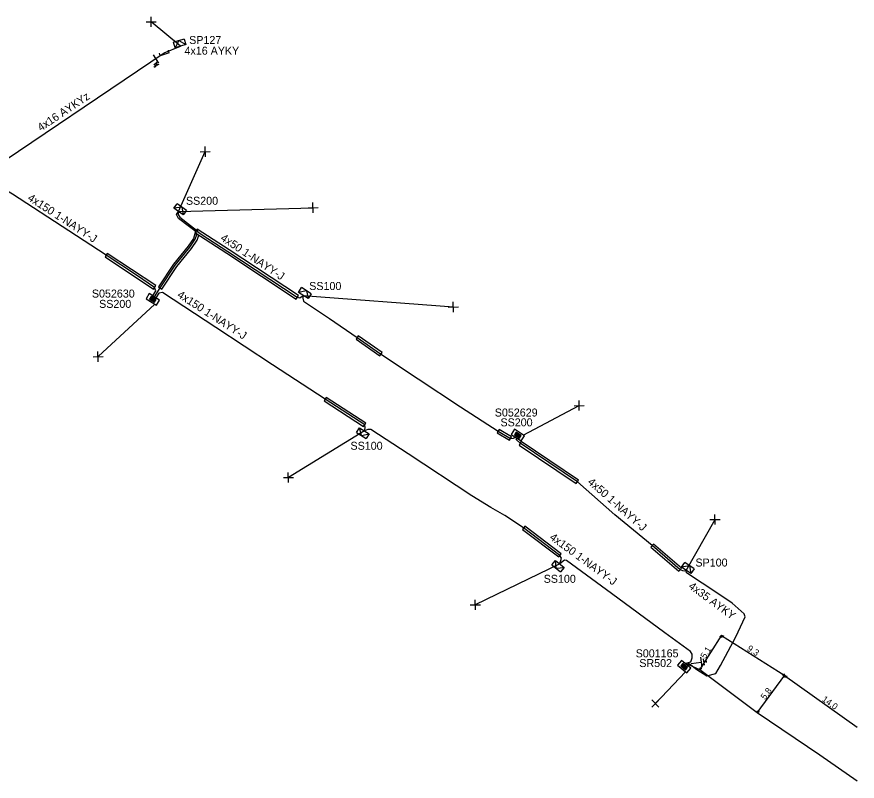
# Model space of a CAD drawing. Extents: x -762504 to -761250, y -1152974 to -1152253.
# Drawn here: x -761354.4 to -761250, y -1152626.9 to -1152531.9 of the extents above; entities that cross this region are included whole.
import ezdxf

# ---------------------------------------------------------------- set-up
doc = ezdxf.new("R2010")
doc.units = 0
for name, color, linetype in [('Vrstva 13', 7, 'Continuous'), ('Vrstva 15', 7, 'Continuous'), ('Vrstva 18', 7, 'Continuous'), ('Vrstva 20', 7, 'Continuous'), ('Vrstva 28', 7, 'Continuous'), ('Vrstva 29', 7, 'Continuous'), ('Vrstva 30', 7, 'Continuous'), ('Vrstva 31', 7, 'Continuous'), ('Vrstva 33', 7, 'Continuous'), ('Vrstva 34', 7, 'Continuous'), ('Vrstva 40', 7, 'Continuous'), ('Vrstva 5', 7, 'Continuous'), ('Vrstva 52', 7, 'Continuous'), ('Vrstva 53', 7, 'Continuous'), ('Vrstva 54', 7, 'Continuous'), ('Vrstva 59', 7, 'Continuous'), ('Vrstva 6', 7, 'Continuous')]:
    doc.layers.add(name, color=color, linetype=linetype)

msp = doc.modelspace()

# ---------------------------------------------------------------- linework, layer by layer
at = {"layer": 'Vrstva 13'}
for points in [[(-761336.618, -1152536.72), (-761336.727, -1152536.383)], [(-761335.494, -1152536.355), (-761336.618, -1152536.72)], [(-761335.494, -1152536.355), (-761335.604, -1152536.018)]]:
    msp.add_lwpolyline(points, dxfattribs=at)
at = {"layer": 'Vrstva 15'}
for points in [[(-761269.486, -1152611.464), (-761269.312, -1152612.702)], [(-761269.145, -1152611.659), (-761269.036, -1152612.439)], [(-761268.799, -1152611.864), (-761268.78, -1152611.996)], [(-761268.78, -1152611.996), (-761268.762, -1152612.123)], [(-761270.637, -1152612.257), (-761269.399, -1152612.083)]]:
    msp.add_lwpolyline(points, dxfattribs=at)
at = {"layer": 'Vrstva 18'}
for points in [[(-761337.514, -1152536.595), (-761336.815, -1152537.631)], [(-761337.401, -1152537.73), (-761337.219, -1152537.999)], [(-761337.23, -1152537.614), (-761336.999, -1152537.957)], [(-761337.087, -1152537.826), (-761337.058, -1152537.499)], [(-761337.076, -1152537.718), (-761336.799, -1152537.822)], [(-761337.391, -1152538.115), (-761337.418, -1152538.074)], [(-761337.348, -1152538.151), (-761337.391, -1152538.115)], [(-761337.268, -1152538.139), (-761337.348, -1152538.151)], [(-761337.243, -1152538.122), (-761337.268, -1152538.139)], [(-761337.206, -1152538.055), (-761337.243, -1152538.122)], [(-761337.219, -1152537.999), (-761337.206, -1152538.055)]]:
    msp.add_lwpolyline(points, dxfattribs=at)
at = {"layer": 'Vrstva 20'}
for points in [[(-761332.04, -1152558.25), (-761332.32, -1152558.67), (-761328.34, -1152561.26), (-761319.73, -1152566.95), (-761319.45, -1152566.53), (-761328.06, -1152560.84)], [(-761336.85, -1152565.43), (-761336.43, -1152565.71), (-761334.55, -1152562.91), (-761332.75, -1152560.67), (-761332.03, -1152559.63), (-761331.83, -1152559.01), (-761332.31, -1152558.85), (-761332.49, -1152559.41), (-761333.15, -1152560.37), (-761334.96, -1152562.63)], [(-761343.48, -1152561.71), (-761337.45, -1152565.71), (-761337.17, -1152565.29), (-761343.2, -1152561.29)], [(-761312, -1152571.52), (-761312.28, -1152571.92), (-761309.31, -1152574.02), (-761309.03, -1152573.61)], [(-761315.99, -1152579.19), (-761316.26, -1152579.61), (-761311.34, -1152582.78), (-761311.07, -1152582.36)], [(-761294.76, -1152583.57), (-761293.21, -1152584.5), (-761292.95, -1152584.08), (-761294.5, -1152583.15)], [(-761292.02, -1152585.09), (-761284.92, -1152589.86), (-761284.64, -1152589.44), (-761291.74, -1152584.67)], [(-761291.31, -1152595.17), (-761291.61, -1152595.57), (-761287.1, -1152599), (-761286.8, -1152598.6)], [(-761275.31, -1152597.39), (-761275.63, -1152597.77), (-761272.16, -1152600.77), (-761271.84, -1152600.39)]]:
    msp.add_lwpolyline(points, close=True, dxfattribs=at)
at = {"layer": 'Vrstva 28'}
for points in [[(-761337.972, -1152566.28), (-761338.37, -1152566.917)], [(-761338.37, -1152566.917), (-761337.098, -1152567.711)], [(-761336.7, -1152567.075), (-761337.972, -1152566.28)], [(-761337.754, -1152566.633), (-761337.954, -1152566.953)], [(-761337.954, -1152566.953), (-761337.323, -1152567.348)], [(-761337.739, -1152566.698), (-761337.889, -1152566.938)], [(-761337.889, -1152566.938), (-761337.338, -1152567.283)], [(-761337.724, -1152566.763), (-761337.824, -1152566.923)], [(-761337.824, -1152566.923), (-761337.353, -1152567.218)], [(-761337.709, -1152566.828), (-761337.759, -1152566.908)], [(-761337.759, -1152566.908), (-761337.368, -1152567.152)], [(-761337.123, -1152567.027), (-761337.754, -1152566.633)], [(-761337.188, -1152567.042), (-761337.739, -1152566.698)], [(-761337.253, -1152567.057), (-761337.724, -1152566.763)], [(-761337.318, -1152567.072), (-761337.709, -1152566.828)], [(-761337.699, -1152566.89), (-761337.378, -1152567.091)], [(-761337.368, -1152567.152), (-761337.318, -1152567.072)], [(-761337.353, -1152567.218), (-761337.253, -1152567.057)], [(-761337.338, -1152567.283), (-761337.188, -1152567.042)], [(-761337.323, -1152567.348), (-761337.123, -1152567.027)], [(-761337.098, -1152567.711), (-761336.7, -1152567.075)], [(-761292.604, -1152583.134), (-761293.012, -1152583.763)], [(-761293.012, -1152583.763), (-761291.754, -1152584.58)], [(-761291.346, -1152583.951), (-761292.604, -1152583.134)], [(-761292.385, -1152583.502), (-761292.591, -1152583.819)], [(-761292.591, -1152583.819), (-761291.967, -1152584.224)], [(-761292.371, -1152583.567), (-761292.525, -1152583.805)], [(-761292.525, -1152583.805), (-761291.981, -1152584.159)], [(-761292.357, -1152583.632), (-761292.46, -1152583.791)], [(-761292.46, -1152583.791), (-761291.994, -1152584.093)], [(-761292.343, -1152583.698), (-761292.395, -1152583.777)], [(-761292.395, -1152583.777), (-761292.008, -1152584.028)], [(-761291.761, -1152583.907), (-761292.385, -1152583.502)], [(-761291.826, -1152583.921), (-761292.371, -1152583.567)], [(-761291.892, -1152583.935), (-761292.357, -1152583.632)], [(-761291.957, -1152583.949), (-761292.343, -1152583.698)], [(-761292.017, -1152583.966), (-761292.334, -1152583.76)], [(-761292.008, -1152584.028), (-761291.957, -1152583.949)], [(-761291.994, -1152584.093), (-761291.892, -1152583.935)], [(-761291.981, -1152584.159), (-761291.826, -1152583.921)], [(-761291.967, -1152584.224), (-761291.761, -1152583.907)], [(-761291.754, -1152584.58), (-761291.346, -1152583.951)], [(-761271.849, -1152611.877), (-761272.321, -1152612.46)], [(-761270.684, -1152612.821), (-761271.849, -1152611.877)], [(-761272.321, -1152612.46), (-761271.156, -1152613.404)], [(-761271.675, -1152612.253), (-761271.913, -1152612.547)], [(-761271.913, -1152612.547), (-761271.335, -1152613.015)], [(-761271.668, -1152612.32), (-761271.847, -1152612.54)], [(-761271.847, -1152612.54), (-761271.342, -1152612.949)], [(-761271.662, -1152612.386), (-761271.78, -1152612.533)], [(-761271.78, -1152612.533), (-761271.349, -1152612.882)], [(-761271.655, -1152612.453), (-761271.714, -1152612.526)], [(-761271.714, -1152612.526), (-761271.356, -1152612.816)], [(-761271.097, -1152612.722), (-761271.675, -1152612.253)], [(-761271.164, -1152612.729), (-761271.668, -1152612.32)], [(-761271.23, -1152612.736), (-761271.662, -1152612.386)], [(-761271.296, -1152612.743), (-761271.655, -1152612.453)], [(-761271.652, -1152612.515), (-761271.358, -1152612.753)], [(-761271.356, -1152612.816), (-761271.296, -1152612.743)], [(-761271.349, -1152612.882), (-761271.23, -1152612.736)], [(-761271.342, -1152612.949), (-761271.164, -1152612.729)], [(-761271.335, -1152613.015), (-761271.097, -1152612.722)], [(-761271.156, -1152613.404), (-761270.684, -1152612.821)]]:
    msp.add_lwpolyline(points, dxfattribs=at)
at = {"layer": 'Vrstva 31'}
for points in [[(-761333.633, -1152534.645), (-761334.971, -1152535.054)], [(-761333.633, -1152534.645), (-761333.428, -1152535.314), (-761334.767, -1152535.723), (-761334.971, -1152535.054)], [(-761334.302, -1152534.849), (-761334.767, -1152535.723)], [(-761334.302, -1152534.849), (-761333.428, -1152535.314)], [(-761333.37, -1152555.937), (-761333.781, -1152556.503), (-761334.914, -1152555.68), (-761334.503, -1152555.114)], [(-761333.936, -1152555.525), (-761334.914, -1152555.68)], [(-761333.37, -1152555.937), (-761334.503, -1152555.114)], [(-761333.936, -1152555.525), (-761333.781, -1152556.503)], [(-761317.869, -1152566.295), (-761318.25, -1152566.882), (-761319.424, -1152566.12), (-761319.043, -1152565.533)], [(-761318.456, -1152565.914), (-761319.424, -1152566.12)], [(-761317.869, -1152566.295), (-761319.043, -1152565.533)], [(-761318.456, -1152565.914), (-761318.25, -1152566.882)], [(-761312.217, -1152583.541), (-761311.846, -1152582.947), (-761310.659, -1152583.689), (-761311.029, -1152584.283)], [(-761312.217, -1152583.541), (-761311.029, -1152584.283)], [(-761311.623, -1152583.912), (-761311.846, -1152582.947)], [(-761311.623, -1152583.912), (-761310.659, -1152583.689)], [(-761287.947, -1152599.972), (-761287.507, -1152599.428), (-761286.419, -1152600.309), (-761286.859, -1152600.853)], [(-761287.403, -1152600.412), (-761287.507, -1152599.428)], [(-761287.947, -1152599.972), (-761286.859, -1152600.853)], [(-761287.403, -1152600.412), (-761286.419, -1152600.309)], [(-761270.266, -1152600.483), (-761270.657, -1152601.063), (-761271.818, -1152600.28), (-761271.426, -1152599.7)], [(-761270.846, -1152600.091), (-761271.818, -1152600.28)], [(-761270.266, -1152600.483), (-761271.426, -1152599.7)], [(-761270.846, -1152600.091), (-761270.657, -1152601.063)]]:
    msp.add_lwpolyline(points, dxfattribs=at)
at = {"layer": 'Vrstva 34'}
for points in [[(-761338.375, -1152532.521), (-761337.125, -1152532.499)], [(-761337.739, -1152533.135), (-761337.761, -1152531.885)], [(-761331.009, -1152549.265), (-761331.031, -1152548.015)], [(-761331.645, -1152548.651), (-761330.395, -1152548.629)], [(-761318.245, -1152555.611), (-761316.995, -1152555.589)], [(-761317.609, -1152556.225), (-761317.631, -1152554.975)], [(-761300.815, -1152567.951), (-761299.565, -1152567.929)], [(-761300.179, -1152568.565), (-761300.201, -1152567.315)], [(-761344.965, -1152574.121), (-761343.715, -1152574.099)], [(-761344.329, -1152574.735), (-761344.351, -1152573.485)], [(-761284.549, -1152580.815), (-761284.571, -1152579.565)], [(-761285.185, -1152580.201), (-761283.935, -1152580.179)], [(-761320.679, -1152589.755), (-761320.701, -1152588.505)], [(-761321.315, -1152589.141), (-761320.065, -1152589.119)], [(-761267.659, -1152594.975), (-761267.681, -1152593.725)], [(-761268.295, -1152594.361), (-761267.045, -1152594.339)], [(-761297.449, -1152605.575), (-761297.471, -1152604.325)], [(-761298.085, -1152604.961), (-761296.835, -1152604.939)], [(-761275.522, -1152616.768), (-761274.638, -1152617.652)], [(-761275.522, -1152617.652), (-761274.638, -1152616.768)]]:
    msp.add_lwpolyline(points, dxfattribs=at)
at = {"layer": 'Vrstva 40'}
for points in [[(-761269.57, -1152613.03), (-761266.84, -1152608.73)], [(-761266.86, -1152608.75), (-761259, -1152613.72)], [(-761262.43, -1152618.37), (-761258.98, -1152613.69)], [(-761259.02, -1152613.74), (-761250, -1152620.15)]]:
    msp.add_lwpolyline(points, dxfattribs=at)
for points in [[(-761266.838, -1152608.728), (-761266.882, -1152608.994), (-761267.059, -1152608.883)], [(-761266.862, -1152608.748), (-761266.596, -1152608.791), (-761266.707, -1152608.969)], [(-761269.571, -1152613.032), (-761269.528, -1152612.766), (-761269.351, -1152612.877)], [(-761258.998, -1152613.721), (-761259.264, -1152613.678), (-761259.154, -1152613.501)], [(-761258.979, -1152613.688), (-761259.04, -1152613.95), (-761259.209, -1152613.828)], [(-761259.022, -1152613.738), (-761258.758, -1152613.795), (-761258.878, -1152613.966)], [(-761262.432, -1152618.372), (-761262.37, -1152618.109), (-761262.201, -1152618.232)]]:
    msp.add_lwpolyline(points, close=True, dxfattribs=at)
at = {"layer": 'Vrstva 5'}
for points in [[(-761337.55, -1152566.54), (-761337.18, -1152565.94), (-761337.31, -1152565.5), (-761339.55, -1152564), (-761343.34, -1152561.5), (-761347.98, -1152558.48), (-761354.99, -1152553.94), (-761358.69, -1152551.7), (-761359.47, -1152551.32), (-761360.06, -1152550.99), (-761360.59, -1152551.08), (-761360.85, -1152551.35)], [(-761337.34, -1152566.68), (-761336.64, -1152565.57), (-761334.75, -1152562.76), (-761332.95, -1152560.52), (-761332.26, -1152559.52), (-761332.07, -1152558.93), (-761332.14, -1152558.61), (-761332.96, -1152557.99), (-761334.33, -1152556.94), (-761334.59, -1152556.45), (-761334.35, -1152556.09), (-761334.37, -1152556.43), (-761334.17, -1152556.8), (-761332.84, -1152557.83), (-761332.12, -1152558.38), (-761331.96, -1152558.61), (-761331.53, -1152558.9), (-761328.2, -1152561.05), (-761319.59, -1152566.74), (-761319.25, -1152566.8), (-761318.84, -1152566.5), (-761318.89, -1152566.86), (-761318.81, -1152567.2), (-761315.58, -1152569.37), (-761312.14, -1152571.72), (-761309.36, -1152573.68), (-761304.58, -1152576.86), (-761299.29, -1152580.33), (-761294.63, -1152583.36), (-761293.08, -1152584.29), (-761292.7, -1152584.24), (-761292.48, -1152584.1)], [(-761271.41, -1152612.24), (-761270.67, -1152612.04), (-761270.5, -1152611.53), (-761270.51, -1152611.08), (-761270.7, -1152610.76), (-761273.91, -1152608.43), (-761280.53, -1152603.55), (-761286.14, -1152599.44), (-761286.39, -1152599.39), (-761286.96, -1152599.87), (-761286.75, -1152599.15), (-761286.95, -1152598.8), (-761291.46, -1152595.37), (-761293.78, -1152593.83), (-761295.52, -1152592.85), (-761297.91, -1152591.39), (-761305.81, -1152586.17), (-761310.45, -1152583.16), (-761310.81, -1152583.16), (-761311.25, -1152583.32), (-761311.13, -1152582.95), (-761311.2, -1152582.57), (-761316.12, -1152579.4), (-761322.67, -1152575.13), (-761329.72, -1152570.49), (-761336.32, -1152566.16), (-761336.78, -1152566.24), (-761337.15, -1152566.8)], [(-761271.24, -1152600.67), (-761271.56, -1152600.78), (-761272, -1152600.58), (-761275.47, -1152597.58), (-761280.1, -1152593.77), (-761284.78, -1152589.65), (-761291.88, -1152584.88), (-761292.37, -1152584.42), (-761292.3, -1152584.23)], [(-761271.27, -1152612.35), (-761270.89, -1152612.25), (-761269.93, -1152612.98), (-761268.68, -1152613.79), (-761267.55, -1152613.49), (-761266.98, -1152612.48), (-761265.07, -1152608.93), (-761263.94, -1152606.43), (-761264.04, -1152606.06), (-761265.54, -1152604.76), (-761267.31, -1152603.52), (-761271.2, -1152600.97), (-761271.24, -1152600.67)], [(-761250, -1152626.86), (-761254.65, -1152623.62), (-761262.43, -1152618.37), (-761269.57, -1152613.03), (-761270.94, -1152612.41), (-761271.16, -1152612.45)]]:
    msp.add_lwpolyline(points, dxfattribs=at)
at = {"layer": 'Vrstva 52'}
for points in [[(-761336.11, -1152536.37), (-761334.1, -1152535.52)], [(-761359.26, -1152551.93), (-761336.11, -1152536.37)]]:
    msp.add_lwpolyline(points, dxfattribs=at)
at = {"layer": 'Vrstva 59'}
for points in [[(-761334.1, -1152535.52), (-761337.75, -1152532.51)], [(-761334.35, -1152556.09), (-761331.02, -1152548.64)], [(-761334.35, -1152556.09), (-761317.62, -1152555.6)], [(-761318.84, -1152566.5), (-761300.19, -1152567.94)], [(-761337.3, -1152567.6), (-761344.34, -1152574.11)], [(-761291.5, -1152583.85), (-761284.56, -1152580.19)], [(-761311.25, -1152583.32), (-761320.69, -1152589.13)], [(-761271.24, -1152600.67), (-761267.67, -1152594.35)], [(-761286.96, -1152599.87), (-761297.46, -1152604.95)], [(-761271.33, -1152613.29), (-761275.08, -1152617.21)]]:
    msp.add_lwpolyline(points, dxfattribs=at)

# ---------------------------------------------------------------- texts
at = {"layer": 'Vrstva 29'}
for s, p in [('S052630', (-761345.11, -1152566.77)), ('S052629', (-761295.04, -1152581.55)), ('S001165', (-761277.53, -1152611.47))]:
    msp.add_text(s, height=0.9943, dxfattribs=at).set_placement(p)
at = {"layer": 'Vrstva 30'}
for s, p in [('SS200', (-761344.21, -1152568.05)), ('SS200', (-761294.33, -1152582.77)), ('SR502', (-761277.08, -1152612.68))]:
    msp.add_text(s, height=0.9943, dxfattribs=at).set_placement(p)
at = {"layer": 'Vrstva 33'}
for s, p in [('SP127', (-761333.02, -1152535.26)), ('SS200', (-761333.42, -1152555.24)), ('SS100', (-761318.1, -1152565.83)), ('SS100', (-761312.97, -1152585.68)), ('SP100', (-761270.1, -1152600.19)), ('SS100', (-761288.96, -1152602.21))]:
    msp.add_text(s, height=0.9943, dxfattribs=at).set_placement(p)
at = {"layer": 'Vrstva 40'}
for s, rotation, p in [('5,1', 57.60043, (-761268.87, -1152611.71)), ('9,3', 327.71054, (-761263.76, -1152610.57)), ('5,8', 53.61364, (-761261.43, -1152616.81)), ('14,0', 324.62209, (-761254.45, -1152616.84))]:
    msp.add_text(s, height=0.7954, rotation=rotation, dxfattribs=at).set_placement(p)
at = {"layer": 'Vrstva 53'}
msp.add_text('4x16 AYKYz', height=0.9943, rotation=33.90541, dxfattribs=at).set_placement((-761351.46, -1152546.16))
at = {"layer": 'Vrstva 54'}
msp.add_text('4x16 AYKY', height=0.9943, dxfattribs=at).set_placement((-761333.6, -1152536.59))
at = {"layer": 'Vrstva 6'}
for s, height, rotation, p in [('4x150 1-NAYY-J', 0.99428, 327.07104, (-761353.19, -1152554.62)), ('4x50 1-NAYY-J', 0.99429, 326.36529, (-761329.22, -1152559.59)), ('4x150 1-NAYY-J', 0.99429, 327.02825, (-761334.59, -1152566.65)), ('4x50 1-NAYY-J', 0.99429, 318.64119, (-761283.58, -1152589.81)), ('4x150 1-NAYY-J', 0.99429, 323.77274, (-761288.31, -1152596.74)), ('4x35 AYKY', 0.9943, 323.60684, (-761271.05, -1152602.81))]:
    msp.add_text(s, height=height, rotation=rotation, dxfattribs=at).set_placement(p)

doc.saveas('drawing.dxf')
